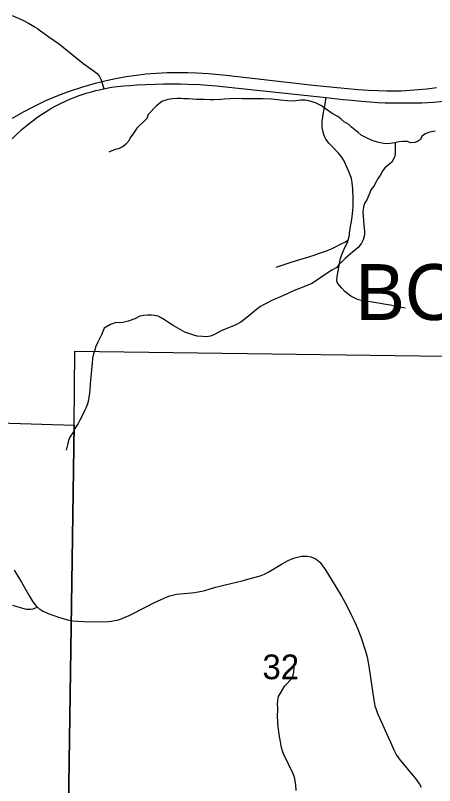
# Model space of a CAD drawing. Extents: x 0 to 34, y 0 to 22.
# Drawn here: x 3.604 to 4.314, y 16.248 to 17.555 of the extents above; entities that cross this region are included whole.
import ezdxf

# ---------------------------------------------------------------- set-up
doc = ezdxf.new("R2010")
doc.units = 0
for name, color, linetype in [('GM_X_Corporation', 7, 'Continuous'), ('GM_X_County_Road', 7, 'Continuous'), ('GM_X_County_Road_Text', 7, 'Continuous'), ('GM_X_Interchange_Ramps', 7, 'Continuous'), ('GM_X_Interstate_Route', 7, 'Continuous'), ('GM_X_Major_River_Text', 7, 'Continuous'), ('GM_X_Minor_Lake', 7, 'Continuous'), ('GM_X_Township_Road_Text', 7, 'Continuous')]:
    doc.layers.add(name, color=color, linetype=linetype)

msp = doc.modelspace()

# ---------------------------------------------------------------- linework, layer by layer
at = {"layer": 'GM_X_Corporation'}
msp.add_lwpolyline([(3.6014, 16.6136), (3.6079, 16.6031), (3.614, 16.5932), (3.6237, 16.576), (3.628, 16.5683), (3.6317, 16.5624), (3.6334, 16.5597), (3.6375, 16.5544), (3.6396, 16.5521), (3.6411, 16.5506), (3.6422, 16.5495), (3.6441, 16.548), (3.647, 16.546), (3.6502, 16.5442), (3.6546, 16.5421), (3.6593, 16.54), (3.6652, 16.5376), (3.6704, 16.5358), (3.6781, 16.5332), (3.6845, 16.5313), (3.6921, 16.5293), (3.701, 16.5278), (3.7096, 16.5268), (3.7189, 16.5264), (3.7303, 16.5261), (3.7615, 16.5265), (3.7663, 16.527), (3.7715, 16.5279), (3.7763, 16.5289), (3.7818, 16.5305), (3.7848, 16.5315), (3.7911, 16.5341), (3.7951, 16.536), (3.8022, 16.5395), (3.8408, 16.559), (3.8495, 16.5632), (3.8556, 16.566), (3.8608, 16.5681), (3.8653, 16.5698), (3.8701, 16.5712), (3.8746, 16.5722), (3.8766, 16.5726), (3.8831, 16.5732), (3.8965, 16.5746), (3.9071, 16.5758), (3.9135, 16.5767), (3.9223, 16.5784), (3.925, 16.5791), (3.9429, 16.5845), (3.9478, 16.586), (3.9592, 16.5889), (3.9878, 16.5957), (3.9977, 16.5981), (4.0126, 16.6022), (4.0185, 16.604), (4.0232, 16.6057), (4.0261, 16.6069), (4.0334, 16.6106), (4.0363, 16.6122), (4.0546, 16.6235), (4.0607, 16.6272), (4.0661, 16.63), (4.0712, 16.6321), (4.0754, 16.6337), (4.0795, 16.6351), (4.0842, 16.6362), (4.0884, 16.637), (4.0921, 16.6373), (4.0953, 16.6374), (4.0989, 16.6372), (4.1017, 16.6367), (4.105, 16.6359), (4.1085, 16.6346), (4.11, 16.6339), (4.1134, 16.6322), (4.1164, 16.63), (4.1191, 16.6275), (4.1202, 16.6264), (4.1262, 16.6185), (4.1282, 16.6156), (4.1346, 16.6056), (4.1408, 16.5955), (4.147, 16.5853), (4.1565, 16.5692), (4.1619, 16.5594), (4.1658, 16.5519), (4.1737, 16.5367), (4.1779, 16.5277), (4.1813, 16.52), (4.1842, 16.5135), (4.1893, 16.5005), (4.1911, 16.4953), (4.1965, 16.478), (4.1976, 16.4742), (4.1994, 16.468), (4.2005, 16.4633), (4.2029, 16.4506), (4.2036, 16.447), (4.2113, 16.3928), (4.2122, 16.3872), (4.2132, 16.3828), (4.2144, 16.3787), (4.2162, 16.3739), (4.2181, 16.3693), (4.2265, 16.3505), (4.2329, 16.3364), (4.2396, 16.3218), (4.2454, 16.3088), (4.2476, 16.3043), (4.2499, 16.3), (4.2527, 16.2958), (4.2562, 16.2911), (4.2781, 16.2645), (4.2818, 16.26), (4.2886, 16.2504), (4.2916, 16.2455)], dxfattribs=at)
at = {"layer": 'GM_X_County_Road'}
msp.add_lwpolyline([(3.5985, 17.3802), (3.6175, 17.391), (3.6361, 17.4007), (3.6553, 17.4099), (3.6744, 17.4179), (3.6939, 17.4254), (3.7177, 17.4334), (3.7393, 17.4395), (3.755, 17.4436), (3.7734, 17.4475), (3.7912, 17.4507), (3.8089, 17.4533), (3.825, 17.4552), (3.8421, 17.4566), (3.8608, 17.4576), (3.8801, 17.4578), (3.8951, 17.4578), (3.9104, 17.4569), (3.9307, 17.4558), (3.9609, 17.453), (4.1086, 17.4363), (4.161, 17.4313), (4.1841, 17.4291), (4.2021, 17.4278), (4.2183, 17.427), (4.2327, 17.4264), (4.2444, 17.4264), (4.2575, 17.4267), (4.2722, 17.4276), (4.2868, 17.4287), (4.3013, 17.4302), (4.3175, 17.4322)], dxfattribs=at)
at = {"layer": 'GM_X_Interchange_Ramps'}
msp.add_lwpolyline([(3.5981, 17.3454), (3.6043, 17.3516), (3.6152, 17.3618), (3.6206, 17.3662), (3.627, 17.3713), (3.6338, 17.3763), (3.6419, 17.3825), (3.6497, 17.3878), (3.6586, 17.3933), (3.6638, 17.3964), (3.672, 17.4009), (3.6803, 17.4051), (3.6887, 17.409), (3.696, 17.4123), (3.7062, 17.4164), (3.7133, 17.419), (3.7234, 17.4224), (3.7324, 17.4251), (3.7401, 17.4272), (3.7482, 17.4291), (3.7535, 17.4302), (3.7609, 17.4316), (3.7669, 17.4326), (3.7763, 17.4338), (3.7873, 17.4349), (3.7975, 17.4358), (3.8096, 17.4366), (3.8246, 17.4373), (3.8406, 17.4379), (3.8547, 17.4383), (3.8701, 17.4384), (3.8837, 17.4383), (3.896, 17.438), (3.9167, 17.4371), (3.9294, 17.4362), (3.9444, 17.435), (3.9759, 17.4318), (4.0245, 17.4265), (4.0398, 17.4248), (4.1304, 17.415), (4.1593, 17.4119), (4.1737, 17.4105), (4.1901, 17.4089), (4.2049, 17.4077), (4.2181, 17.4069), (4.2304, 17.4064), (4.252, 17.406), (4.2857, 17.4062), (4.2924, 17.4064), (4.3131, 17.4076), (4.329, 17.4088)], dxfattribs=at)
at = {"layer": 'GM_X_Interstate_Route'}
for points in [[(3.5982, 17.5545), (3.6071, 17.5505), (3.6171, 17.5456), (3.6256, 17.5413), (3.6328, 17.5374), (3.6373, 17.5346), (3.6409, 17.5322), (3.646, 17.5286), (3.6542, 17.5226), (3.6602, 17.5184), (3.6781, 17.5056), (3.6819, 17.5028), (3.7082, 17.4815), (3.7182, 17.4737), (3.7276, 17.4667), (3.7356, 17.4609), (3.7399, 17.4578), (3.7421, 17.456), (3.7446, 17.453), (3.7462, 17.4506), (3.7482, 17.4464), (3.7495, 17.4429), (3.751, 17.4381), (3.7535, 17.4302)], [(4.1254, 17.3862), (4.1287, 17.4046), (4.1304, 17.415)], [(4.1586, 17.3112), (4.1569, 17.3138), (4.1533, 17.3186), (4.1513, 17.321), (4.1387, 17.3341), (4.1352, 17.3378), (4.132, 17.3417), (4.1301, 17.3445), (4.1294, 17.3456), (4.1283, 17.348), (4.1271, 17.3506), (4.1259, 17.3542), (4.1246, 17.3592), (4.1239, 17.3642), (4.1237, 17.3699), (4.1239, 17.3746), (4.1243, 17.3792), (4.1253, 17.3852), (4.1254, 17.3862)], [(4.2645, 17.0578), (4.2559, 17.0595), (4.2494, 17.0609), (4.2395, 17.0629), (4.2285, 17.0647), (4.2225, 17.0657), (4.2154, 17.0669), (4.2058, 17.0684), (4.198, 17.0697), (4.1941, 17.0703), (4.1905, 17.0709), (4.1855, 17.0723), (4.1824, 17.0734), (4.1788, 17.0749), (4.1759, 17.0765), (4.1725, 17.0785), (4.1672, 17.082), (4.1624, 17.086), (4.1569, 17.0916), (4.1529, 17.0964), (4.1507, 17.0993), (4.1492, 17.1019), (4.1485, 17.1046), (4.149, 17.1115), (4.1506, 17.1209), (4.1523, 17.1302), (4.1535, 17.1365), (4.1549, 17.1422), (4.1567, 17.1475), (4.1578, 17.1502), (4.1594, 17.1541), (4.1624, 17.1606), (4.167, 17.1706), (4.1674, 17.1718), (4.1678, 17.1732), (4.1689, 17.1773), (4.1699, 17.1823), (4.1703, 17.1849), (4.1719, 17.1962), (4.1733, 17.2051), (4.1745, 17.2127), (4.1753, 17.2185), (4.1758, 17.2235), (4.1762, 17.2301), (4.1763, 17.2372), (4.1762, 17.2483), (4.1759, 17.256), (4.1755, 17.2608), (4.1751, 17.265), (4.1744, 17.2708), (4.1732, 17.2776), (4.1726, 17.2796), (4.1717, 17.2824), (4.1707, 17.2852), (4.1686, 17.2908), (4.1656, 17.2973), (4.1617, 17.306), (4.1608, 17.3078), (4.1597, 17.3095), (4.1586, 17.3112)], [(4.0456, 17.1277), (4.0677, 17.135), (4.0801, 17.1387), (4.0955, 17.1433), (4.1102, 17.148), (4.1176, 17.1505), (4.1308, 17.1552), (4.1394, 17.1586), (4.142, 17.1598), (4.1488, 17.1633), (4.1537, 17.1659), (4.1632, 17.1706), (4.1678, 17.1732)], [(3.5989, 16.5544), (3.6044, 16.5527), (3.6119, 16.5503), (3.6177, 16.5486), (3.6221, 16.5476), (3.6249, 16.5473), (3.6299, 16.5474), (3.6337, 16.548), (3.635, 16.5483), (3.6411, 16.5506)]]:
    msp.add_lwpolyline(points, dxfattribs=at)
at = {"layer": 'GM_X_Minor_Lake'}
for points in [[(3.7042, 16.9849), (4.539, 16.9739), (4.5275, 15.9394), (3.6897, 15.9465), (3.703, 16.8594)], [(3.703, 16.8594), (3.6897, 15.9465), (3.688, 15.8589), (2.684, 15.8792), (2.6993, 16.8906)]]:
    msp.add_lwpolyline(points, close=True, dxfattribs=at)
at = {"layer": 'GM_X_Township_Road_Text'}
for points in [[(3.9331, 17.4115), (3.9236, 17.4117), (3.9156, 17.412), (3.9107, 17.4119), (3.9039, 17.4122), (3.8971, 17.4128), (3.8891, 17.4131), (3.8834, 17.4134), (3.8781, 17.4133), (3.8698, 17.4128), (3.8619, 17.4119), (3.8521, 17.4083), (3.8423, 17.4006), (3.8289, 17.3866), (3.8264, 17.3794), (3.8092, 17.3635), (3.8025, 17.3531), (3.7984, 17.3466), (3.7959, 17.3416), (3.791, 17.3362), (3.7862, 17.3319), (3.7786, 17.328), (3.7726, 17.3268), (3.7632, 17.3232), (3.7622, 17.3227)], [(4.3151, 17.3579), (4.3057, 17.3562), (4.2989, 17.3534), (4.2929, 17.3495), (4.2903, 17.3442), (4.2855, 17.3407), (4.2806, 17.3387), (4.2738, 17.3382), (4.2684, 17.3404), (4.2605, 17.3407), (4.254, 17.3398), (4.2465, 17.3386), (4.2348, 17.3365), (4.2276, 17.3371), (4.2177, 17.3393), (4.2082, 17.3422), (4.1998, 17.3462), (4.1899, 17.3514), (4.1845, 17.3559), (4.1734, 17.3649), (4.1688, 17.3697), (4.1612, 17.3738), (4.1558, 17.3787), (4.1501, 17.3828), (4.1409, 17.3884), (4.1329, 17.3936), (4.1225, 17.401), (4.1126, 17.4062), (4.1012, 17.4098), (4.0948, 17.4109), (4.0876, 17.4108), (4.0747, 17.4091), (4.0641, 17.4097), (4.0527, 17.4106), (4.0376, 17.4123), (4.0235, 17.4132), (3.9993, 17.4129), (3.9879, 17.4131), (3.9754, 17.4133), (3.9675, 17.4131), (3.9577, 17.4126), (3.9527, 17.4121), (3.9403, 17.4112), (3.9331, 17.4115)], [(4.2472, 17.3387), (4.2475, 17.3195), (4.2465, 17.3142), (4.242, 17.3057), (4.2357, 17.3007), (4.2304, 17.2968), (4.2263, 17.2914), (4.2219, 17.283), (4.2182, 17.278), (4.2153, 17.2722), (4.2112, 17.2649), (4.206, 17.2587), (4.2045, 17.2534), (4.2023, 17.2484), (4.2001, 17.2427), (4.1957, 17.2357), (4.1935, 17.23), (4.1929, 17.2209), (4.193, 17.2136), (4.1935, 17.2068), (4.1943, 17.1988), (4.1948, 17.1935), (4.1956, 17.1878), (4.1957, 17.1821), (4.1932, 17.174), (4.1902, 17.1683), (4.1847, 17.1609), (4.1719, 17.1501), (4.1626, 17.1423), (4.1577, 17.1369), (4.1518, 17.1319), (4.1484, 17.1269), (4.1402, 17.1226), (4.1338, 17.1183), (4.1214, 17.1097), (4.1139, 17.105), (4.1064, 17.1), (4.0996, 17.0972), (4.0895, 17.0929), (4.0763, 17.0877), (4.0646, 17.0822), (4.0533, 17.0771), (4.0447, 17.0735), (4.0372, 17.0704), (4.0308, 17.0668), (4.0251, 17.0641), (4.0191, 17.061), (4.0124, 17.0555), (3.9989, 17.0443), (3.9911, 17.0381), (3.9858, 17.0342), (3.9775, 17.0299), (3.9708, 17.0271), (3.9648, 17.0243), (3.9591, 17.0224), (3.9527, 17.0196), (3.9414, 17.0133), (3.9343, 17.0106), (3.9275, 17.0093), (3.9207, 17.0096), (3.9119, 17.0102), (3.9059, 17.012), (3.8994, 17.0146), (3.891, 17.0175), (3.883, 17.022), (3.8712, 17.0286), (3.8631, 17.0335), (3.8566, 17.0379), (3.8505, 17.0413), (3.8456, 17.0442), (3.8391, 17.0453), (3.8342, 17.046), (3.8278, 17.0459), (3.8213, 17.0454), (3.8145, 17.0441), (3.8059, 17.0398), (3.7946, 17.0358), (3.7859, 17.0334), (3.7802, 17.0333), (3.7745, 17.0336), (3.7647, 17.0304), (3.7542, 17.0242), (3.7495, 17.0127), (3.7454, 17.0046), (3.7429, 16.9989), (3.7396, 16.9916), (3.7381, 16.9866), (3.7359, 16.9805), (3.7345, 16.9729), (3.7335, 16.9641), (3.7325, 16.9538), (3.7319, 16.9473), (3.7316, 16.9412), (3.7309, 16.9359), (3.7306, 16.9298), (3.73, 16.9206), (3.729, 16.913), (3.7283, 16.9077), (3.7276, 16.9016), (3.7258, 16.8954), (3.7232, 16.8885)], [(3.7232, 16.8885), (3.7196, 16.8816), (3.7163, 16.874), (3.7129, 16.8678), (3.71, 16.8621), (3.7044, 16.854), (3.7019, 16.8479), (3.6959, 16.839), (3.6938, 16.8333), (3.6923, 16.8283), (3.6909, 16.8214), (3.6895, 16.817)], [(4.073, 16.2723), (4.0695, 16.2783), (4.0667, 16.2847), (4.0585, 16.3006), (4.0558, 16.3082), (4.0542, 16.3154), (4.0529, 16.3226), (4.0517, 16.3283), (4.0508, 16.3347), (4.0504, 16.3401), (4.0491, 16.3476), (4.0483, 16.3541), (4.0481, 16.3689), (4.0488, 16.3739), (4.0487, 16.38), (4.0482, 16.3861), (4.0485, 16.3925), (4.0499, 16.399), (4.0603, 16.4171), (4.0722, 16.4298), (4.0748, 16.4352), (4.0754, 16.4405), (4.0761, 16.4485), (4.076, 16.4543)], [(4.0795, 16.24), (4.0793, 16.2495), (4.0769, 16.2624), (4.073, 16.2723)]]:
    msp.add_lwpolyline(points, dxfattribs=at)

# ---------------------------------------------------------------- texts
at = {"layer": 'GM_X_County_Road_Text'}
msp.add_text('32', height=0.04186, rotation=0, dxfattribs=at).set_placement((4.0224, 16.4286))
at = {"layer": 'GM_X_Major_River_Text'}
msp.add_text('BOWERSTON', height=0.0947, rotation=0, dxfattribs=at).set_placement((4.1798, 17.0379))

doc.saveas('drawing.dxf')
